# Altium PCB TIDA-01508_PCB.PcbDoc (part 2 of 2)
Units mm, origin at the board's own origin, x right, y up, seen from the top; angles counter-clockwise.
Board outline 58.5 x 103 mm, 4 copper layers (Top Layer, GND, VCC, Bottom Layer), stack 1.565 mm thick; 194 components, 119 nets, 642 pads, 130 vias.
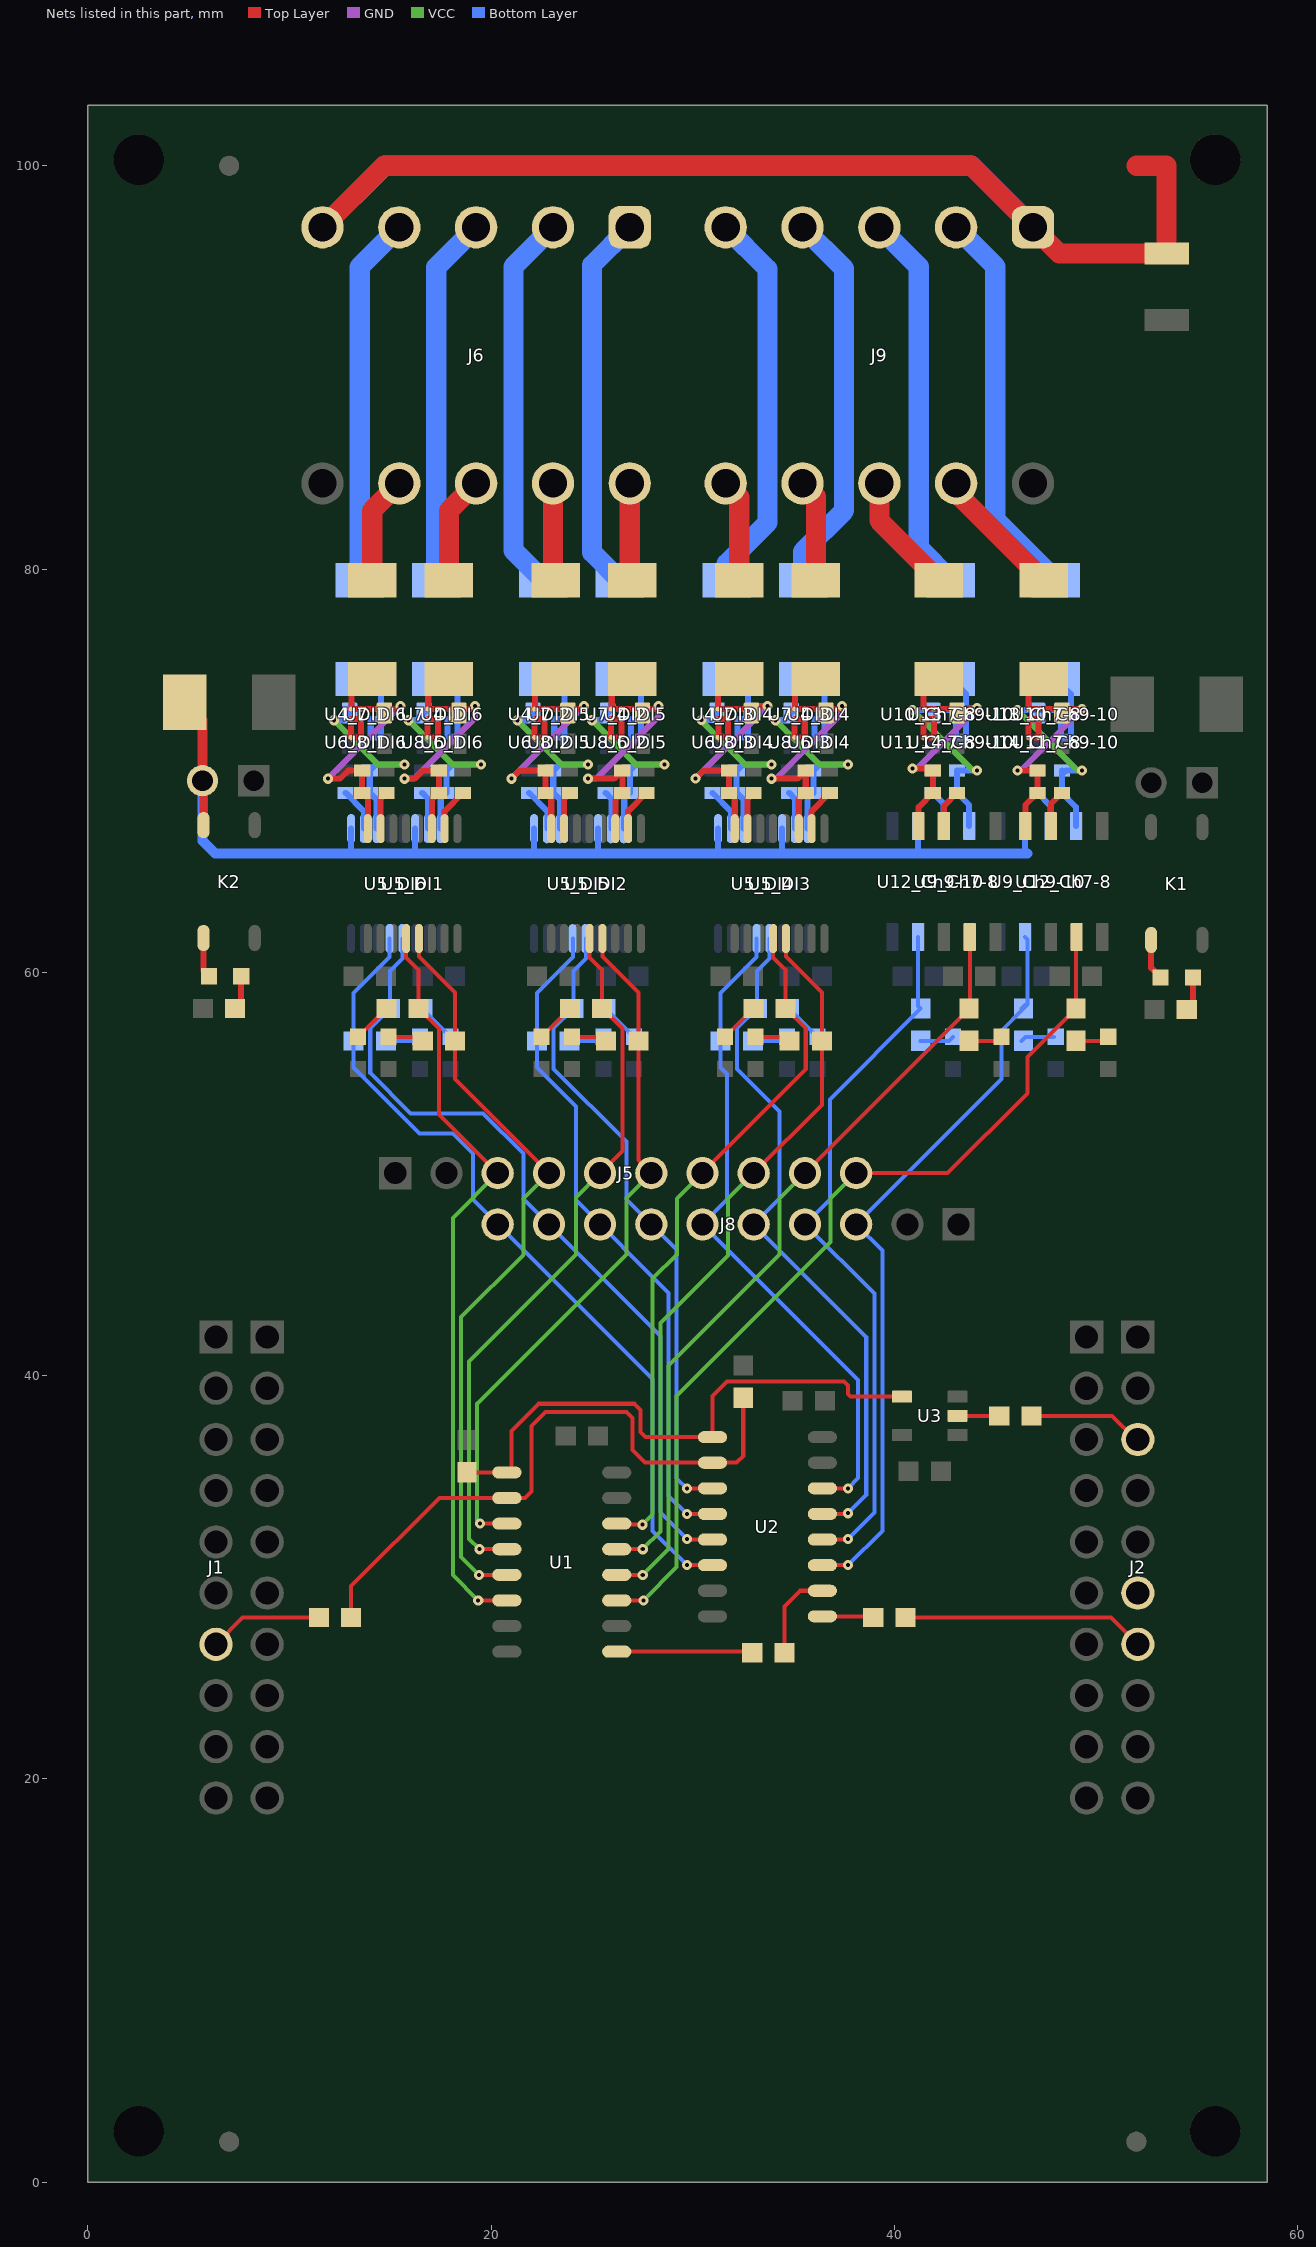
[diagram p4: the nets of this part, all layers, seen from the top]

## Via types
v1: diameter 0.5, hole 0.2, Top Layer to Bottom Layer, 129 vias
v2: diameter 0.7, hole 0.4, Top Layer to Bottom Layer, 1 vias

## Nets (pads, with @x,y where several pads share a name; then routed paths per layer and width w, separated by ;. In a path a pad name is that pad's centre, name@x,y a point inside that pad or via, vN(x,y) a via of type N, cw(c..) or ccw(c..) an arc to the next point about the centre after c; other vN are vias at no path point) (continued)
FGND_float9-16: D4.2 J10.2 K2.4 U5_DI4.9 U5_DI4.14 U5_DI5.9 U5_DI5.14 U5_DI6.9 U5_DI6.14 U9_Ch9-10.6 U12_Ch9-10.6 | length 60.1
  Top Layer w0.4: J10.2@5.68,69.5 5.73,69.45 K2.4@5.73,67.3
  Top Layer w0.5: D4.2@4.79,73.4 5.68,72.51 J10.2@5.68,69.5
  Bottom Layer w0.3: 13.052,65.948 U5_DI6.9@13.052,67.125 ; 16.227,65.927 U5_DI6.14@16.227,67.125 ; 22.126,66.026 U5_DI5.9@22.126,67.119 ; 25.301,65.901 U5_DI5.14@25.301,67.119 ; 31.252,65.952 U5_DI4.9@31.252,67.125 ; 34.427,66.027 U5_DI4.14@34.427,67.125 ; 41.165,65.965 U12_Ch9-10.6@41.165,67.25 ; 46.465,66.065 U9_Ch9-10.6@46.465,67.25
  Bottom Layer w0.5: J10.2@5.68,69.5 5.68,66.52 6.3,65.9 46.6,65.9
IN11: J6.8 R9_DI1.2 | length 5.4
  Top Layer w1: R9_DI1.2@14.1,79.45 14.1,82.91 J6.8@15.44,84.25
IN12: J6.4 R9_DI2.2 | length 4.9
  Top Layer w1: J6.4@23.06,84.25 23.06,79.59 R9_DI2.2@23.2,79.45
IN13: J9.10 R9_DI3.2 | length 5.1
  Top Layer w1: J9.10@31.63,84.25 32.3,83.58 R9_DI3.2@32.3,79.45
IN14: J9.7 R9_DI4.2 | length 19.2
  Bottom Layer w1: J9.7@35.44,96.95 37.5,94.89 37.5,82.9 35.475,80.875 R9_DI4.2@35.475,79.45
IN15: J6.1 R9_DI5.2 | length 18.8
  Bottom Layer w1: R9_DI5.2@26.375,79.45 25,80.825 25,95.08 J6.1@26.87,96.95
IN16: J6.5 R9_DI6.2 | length 18.3
  Bottom Layer w1: R9_DI6.2@17.275,79.45 17.275,94.975 J6.5@19.25,96.95
IN21: J6.6 R11_DI1.2 | length 5.4
  Top Layer w1: R11_DI1.2@17.9,79.45 17.9,82.9 J6.6@19.25,84.25
IN22: J6.2 R11_DI2.2 | length 4.9
  Top Layer w1: J6.2@26.87,84.25 26.87,79.58 R11_DI2.2@27,79.45
IN23: J9.8 R11_DI3.2 | length 5.1
  Top Layer w1: J9.8@35.44,84.25 36.1,83.59 R11_DI3.2@36.1,79.45
IN24: J9.9 R11_DI4.2 | length 19.2
  Bottom Layer w1: J9.9@31.63,96.95 33.7,94.88 33.7,82.3 31.675,80.275 R11_DI4.2@31.675,79.45
IN25: J6.3 R11_DI5.2 | length 18.9
  Bottom Layer w1: R11_DI5.2@22.575,79.45 21.1,80.925 21.1,94.99 J6.3@23.06,96.95
IN26: J6.7 R11_DI6.2 | length 18.3
  Bottom Layer w1: R11_DI6.2@13.475,79.45 13.475,94.985 J6.7@15.44,96.95
INCh7: J9.6 R15_Ch7-8.2 | length 6
  Top Layer w1: J9.6@39.25,84.25 39.25,82.4 R15_Ch7-8.2@42.2,79.45
INCh8: J9.4 R18_Ch7-8.2 | length 6.6
  Top Layer w1: J9.4@43.06,84.25 43.06,83.79 R18_Ch7-8.2@47.4,79.45
InCh9: J9.3 R15_Ch9-10.2 | length 19.5
  Bottom Layer w1: J9.3@43.06,96.95 45,95.01 45,82.45 R15_Ch9-10.2@48,79.45
InCh10: J9.5 R18_Ch9-10.2 | length 19
  Bottom Layer w1: J9.5@39.25,96.95 41.2,95 41.2,81.05 R18_Ch9-10.2@42.8,79.45
NetC6_DI1_2: C6_DI1.2 D5_DI1.2 R9_DI1.1 R10_DI1.2 U4_DI1.A1 U4_DI1.A2 U5_DI1.16 | length 14.7
  Top Layer w0.3: v1(11.9,69.6) 12.5,69.6 12.9,70 C6_DI1.2@13.6,70 R10_DI1.2@13.6,68.9 13.878,68.622 U5_DI1.16@13.878,67.125 ; U4_DI1.A1@13.05,73.05 U4_DI1.A2@13.55,73.05 v1@15.35,73.05 ; U4_DI1.A1@13.077,73.077 13.077,74.55 R9_DI1.1@14.1,74.55
  GND w0.3: v1(11.9,69.6) v1(15.5,73.2)
NetC6_DI2_2: C6_DI2.2 D5_DI2.2 R9_DI2.1 R10_DI2.2 U4_DI2.A1 U4_DI2.A2 U5_DI2.16 | length 15
  Top Layer w0.3: v1(21,69.6) 21.4,70 C6_DI2.2@22.7,70 R10_DI2.2@22.7,68.9 22.978,68.622 U5_DI2.16@22.978,67.125 ; U4_DI2.A1@22.15,73.05 U4_DI2.A2@22.65,73.05 24.45,73.05 v1(24.6,73.2) ; U4_DI2.A1@22.177,73.077 22.177,74.55 R9_DI2.1@23.2,74.55
  GND w0.3: v1(21,69.6) v1(24.6,73.2)
NetC6_DI3_2: C6_DI3.2 D5_DI3.2 R9_DI3.1 R10_DI3.2 U4_DI3.A1 U4_DI3.A2 U5_DI3.16 | length 14.4
  Top Layer w0.3: v1(30.127,69.606) 30.521,70 C6_DI3.2@31.8,70 R10_DI3.2@31.8,68.9 32.078,68.622 U5_DI3.16@32.078,67.125 ; R9_DI3.1@32.169,74.419 31.568,74.419 31.25,74.101 U4_DI3.A1@31.25,73.05 U4_DI3.A2@31.75,73.05 D5_DI3.2@32.71,73.05 ; D5_DI3.2@32.9,72.86 33.24,73.2 v1(33.7,73.2)
  GND w0.3: v1(30.127,69.606) v1@33.7,73.179
NetC6_DI4_2: C6_DI4.2 D5_DI4.2 R9_DI4.1 R10_DI4.2 U4_DI4.A1 U4_DI4.A2 U5_DI4.16 | length 14.3
  VCC w0.3: v1(34.1,72.5) 36.3,70.3 v1(37.7,70.3)
  Bottom Layer w0.3: v1(34.1,72.5) 34.515,72.5 D5_DI4.2@34.875,72.86 35.065,73.05 U4_DI4.A2@36.025,73.05 U4_DI4.A1@36.525,73.05 36.525,74.175 36.5,74.2 35.825,74.2 R9_DI4.1@35.475,74.55 ; U5_DI4.16@35.697,67.125 35.697,68.622 R10_DI4.2@35.975,68.9 C6_DI4.2@35.975,70 36.275,70.3 v1(37.7,70.3)
NetC6_DI5_2: C6_DI5.2 D5_DI5.2 R9_DI5.1 R10_DI5.2 U4_DI5.A1 U4_DI5.A2 U5_DI5.16 | length 14.3
  VCC w0.3: v1(25,72.5) 27.2,70.3 v1(28.6,70.3)
  Bottom Layer w0.3: v1(25,72.5) 25.415,72.5 D5_DI5.2@25.775,72.86 25.965,73.05 U4_DI5.A2@26.925,73.05 U4_DI5.A1@27.425,73.05 27.425,74.175 27.4,74.2 26.725,74.2 R9_DI5.1@26.375,74.55 ; U5_DI5.16@26.597,67.125 26.597,68.622 R10_DI5.2@26.875,68.9 C6_DI5.2@26.875,70 27.175,70.3 v1(28.6,70.3)
NetC6_DI6_2: C6_DI6.2 D5_DI6.2 R9_DI6.1 R10_DI6.2 U4_DI6.A1 U4_DI6.A2 U5_DI6.16 | length 14.3
  VCC w0.3: v1(15.9,72.5) 18.1,70.3 v1(19.5,70.3)
  Bottom Layer w0.3: v1(15.9,72.5) 16.315,72.5 D5_DI6.2@16.675,72.86 16.865,73.05 U4_DI6.A2@17.825,73.05 U4_DI6.A1@18.325,73.05 18.325,74.175 18.3,74.2 17.625,74.2 R9_DI6.1@17.275,74.55 ; U5_DI6.16@17.497,67.125 17.497,68.622 R10_DI6.2@17.775,68.9 C6_DI6.2@17.775,70 18.075,70.3 v1(19.5,70.3)
NetC7_DI1_2: C7_DI1.2 D6_DI1.2 R11_DI1.1 R12_DI1.2 U5_DI1.11 U7_DI1.A1 U7_DI1.A2 | length 15.1
  Top Layer w0.3: v1(15.7,69.6) 16.2,69.6 16.6,70 C7_DI1.2@17.4,70 R12_DI1.2@17.4,68.9 17.053,68.553 U5_DI1.11@17.053,67.125 ; U7_DI1.A1@16.85,73.05 U7_DI1.A2@17.35,73.05 19.05,73.05 v1(19.2,73.2) ; U7_DI1.A1@16.877,73.077 16.877,74.55 R11_DI1.1@17.9,74.55
  GND w0.3: v1(15.7,69.6) 16.175,69.6 19.2,72.625 v1(19.2,73.2)
NetC7_DI2_2: C7_DI2.2 D6_DI2.2 R11_DI2.1 R12_DI2.2 U5_DI2.11 U7_DI2.A1 U7_DI2.A2 | length 15.1
  Top Layer w0.3: v1(24.8,69.6) 26.1,69.6 C7_DI2.2@26.5,70 R12_DI2.2@26.5,68.9 26.153,68.553 U5_DI2.11@26.153,67.125 ; U7_DI2.A1@25.95,73.05 U7_DI2.A2@26.45,73.05 28.15,73.05 v1(28.3,73.2) ; U7_DI2.A1@25.977,73.077 25.977,74.55 R11_DI2.1@27,74.55
  GND w0.3: v1(24.8,69.6) 25.2,69.6 28.3,72.7 v1(28.3,73.2)
NetC7_DI3_2: C7_DI3.2 D6_DI3.2 R11_DI3.1 R12_DI3.2 U5_DI3.11 U7_DI3.A1 U7_DI3.A2 | length 15
  Top Layer w0.3: v1(33.9,69.6) 35.2,69.6 C7_DI3.2@35.6,70 R12_DI3.2@35.6,68.9 35.253,68.553 U5_DI3.11@35.253,67.125 ; U7_DI3.A1@35.05,73.05 37.25,73.05 v1(37.4,73.2) ; U7_DI3.A1@35.077,73.077 35.077,74.55 R11_DI3.1@36.1,74.55
  GND w0.3: v1(33.9,69.6) 34.125,69.6 37.4,72.875 v1(37.4,73.2)
NetC7_DI4_2: C7_DI4.2 D6_DI4.2 R11_DI4.1 R12_DI4.2 U5_DI4.11 U7_DI4.A1 U7_DI4.A2 | length 14.3
  VCC w0.3: v1@30.4,72.5 32.6,70.3 v1(33.9,70.3)
  Bottom Layer w0.3: v1(30.427,72.506) 30.842,72.506 D6_DI4.2@31.202,72.866 D6_DI4.2@31.392,73.056 ; D6_DI4.2@31.365,73.05 U7_DI4.A2@32.225,73.05 U7_DI4.A1@32.725,73.05 32.725,74.375 32.55,74.55 R11_DI4.1@31.675,74.55 ; U5_DI4.11@32.522,67.125 32.522,68.553 R12_DI4.2@32.175,68.9 C7_DI4.2@32.175,70 32.475,70.3 v1(33.9,70.3)
NetC7_DI5_2: C7_DI5.2 D6_DI5.2 R11_DI5.1 R12_DI5.2 U5_DI5.11 U7_DI5.A1 U7_DI5.A2 | length 14.3
  VCC w0.3: v1(21.3,72.5) 23.5,70.3 v1(24.8,70.3)
  Bottom Layer w0.3: v1(21.3,72.5) 21.715,72.5 D6_DI5.2@22.075,72.86 22.265,73.05 U7_DI5.A2@23.125,73.05 U7_DI5.A1@23.625,73.05 23.625,74.375 23.45,74.55 R11_DI5.1@22.575,74.55 ; U5_DI5.11@23.422,67.125 23.422,68.553 R12_DI5.2@23.075,68.9 C7_DI5.2@23.075,70 23.375,70.3 v1(24.8,70.3)
NetC7_DI6_2: C7_DI6.2 D6_DI6.2 R11_DI6.1 R12_DI6.2 U5_DI6.11 U7_DI6.A1 U7_DI6.A2 | length 14.3
  VCC w0.3: v1(12.2,72.5) 14.4,70.3 v1(15.7,70.3)
  Bottom Layer w0.3: v1(12.2,72.5) 12.615,72.5 D6_DI6.2@12.975,72.86 13.165,73.05 U7_DI6.A2@14.025,73.05 U7_DI6.A1@14.525,73.05 14.525,74.375 14.35,74.55 R11_DI6.1@13.475,74.55 ; U5_DI6.11@14.322,67.125 14.322,68.553 R12_DI6.2@13.975,68.9 C7_DI6.2@13.975,70 14.275,70.3 v1(15.7,70.3)
NetC10_Ch7-8_2: C10_Ch7-8.2 D9_Ch7-8.2 R15_Ch7-8.1 R16_Ch7-8.2 U9_Ch7-8.8 U10_Ch7-8.A1 U10_Ch7-8.A2 | length 13
  Top Layer w0.3: v1(40.9,70.1) 41.8,70.1 C10_Ch7-8.2@41.9,70 R16_Ch7-8.2@41.9,68.9 41.195,68.195 U9_Ch7-8.8@41.195,67.25 ; R15_Ch7-8.1@42.2,74.55 41.45,73.8 U10_Ch7-8.A1@41.45,73.05 U10_Ch7-8.A2@41.95,73.05 42.91,73.05 42.96,73.1 v1(44.1,73.1)
  GND w0.3: v1(40.9,70.1) 41.1,70.1 v1(44.1,73.1)
NetC10_Ch9-10_2: C10_Ch9-10.2 D9_Ch9-10.2 R15_Ch9-10.1 R16_Ch9-10.2 U9_Ch9-10.8 U10_Ch9-10.A1 U10_Ch9-10.A2 | length 13.1
  VCC w0.3: v1(46.1,73) 49.1,70 v1(49.3,70)
  Bottom Layer w0.3: v1(46.1,73) 48.1,73 48.2,73.1 U10_Ch9-10.A2@48.25,73.05 U10_Ch9-10.A1@48.75,73.05 48.75,73.8 R15_Ch9-10.1@48,74.55 ; U9_Ch9-10.8@49.005,67.25 49.005,68.195 R16_Ch9-10.2@48.3,68.9 C10_Ch9-10.2@48.3,70 48.4,69.9 48.5,70 v1(49.3,70)
NetC11_Ch7-8_2: C11_Ch7-8.2 D11_Ch7-8.2 R18_Ch7-8.1 R19_Ch7-8.2 U12_Ch7-8.8 U13_Ch7-8.A1 U13_Ch7-8.A2 | length 12.9
  Top Layer w0.3: v1(46.1,70) C11_Ch7-8.2@47.1,70 R19_Ch7-8.2@47.1,68.9 46.495,68.295 U12_Ch7-8.8@46.495,67.25 ; R18_Ch7-8.1@47.4,74.55 46.65,73.8 U13_Ch7-8.A1@46.65,73.05 U13_Ch7-8.A2@47.15,73.05 48.11,73.05 v1(49.3,73.05)
  GND w0.3: v1(46.1,70) 46.25,70 v1(49.3,73.05)
NetC11_Ch9-10_2: C11_Ch9-10.2 D11_Ch9-10.2 R18_Ch9-10.1 R19_Ch9-10.2 U12_Ch9-10.8 U13_Ch9-10.A1 U13_Ch9-10.A2 | length 13
  VCC w0.3: v1(40.9,73) 43.9,70 v1(44.1,70)
  Bottom Layer w0.3: v1(40.9,73) 42.8,73 42.9,73.1 43,73 U13_Ch9-10.A2@43.05,73.05 U13_Ch9-10.A1@43.55,73.05 43.55,73.8 R18_Ch9-10.1@42.8,74.55 ; U12_Ch9-10.8@43.705,67.25 43.705,68.295 R19_Ch9-10.2@43.1,68.9 C11_Ch9-10.2@43.1,70 v1(44.1,70)
NetD1_1: D1.1 K1.1 | length 2
  Top Layer w0.3: K1.1@52.73,61.6 52.73,60.22 D1.1@53.2,59.75
NetD1_2: D1.2 R1.2 | length 1.7
  Top Layer w0.3: R1.2@54.5,58.15 54.8,58.45 D1.2@54.8,59.75
NetD3_1: D3.1 K2.1 | length 2
  Top Layer w0.3: K2.1@5.73,61.7 5.73,60.07 D3.1@6,59.8
NetD3_2: D3.2 R5.2 | length 1.7
  Top Layer w0.3: R5.2@7.3,58.2 7.6,58.5 D3.2@7.6,59.8
NetD7_DI1_2: D7_DI1.2 R13_DI1.1 | length 2
  Top Layer w0.2: D7_DI1.2@13.4,56.8 R13_DI1.1@14.8,58.2
NetD7_DI2_2: D7_DI2.2 R13_DI2.1 | length 2
  Top Layer w0.2: D7_DI2.2@22.5,56.8 R13_DI2.1@23.9,58.2
NetD7_DI3_2: D7_DI3.2 R13_DI3.1 | length 2
  Top Layer w0.2: D7_DI3.2@31.6,56.8 R13_DI3.1@33,58.2
NetD7_DI4_2: D7_DI4.2 R13_DI4.1 | length 2
  Bottom Layer w0.2: R13_DI4.1@34.775,58.2 D7_DI4.2@36.175,56.8
NetD7_DI5_2: D7_DI5.2 R13_DI5.1 | length 2
  Bottom Layer w0.2: R13_DI5.1@25.675,58.2 D7_DI5.2@27.075,56.8
NetD7_DI6_2: D7_DI6.2 R13_DI6.1 | length 2
  Bottom Layer w0.2: R13_DI6.1@16.575,58.2 D7_DI6.2@17.975,56.8
NetD8_DI1_2: D8_DI1.2 R14_DI1.1 | length 1.8
  Top Layer w0.2: D8_DI1.2@14.9,56.8 16.4,56.8 R14_DI1.1@16.6,56.6
NetD8_DI2_2: D8_DI2.2 R14_DI2.1 | length 1.8
  Top Layer w0.2: D8_DI2.2@24,56.8 25.5,56.8 R14_DI2.1@25.7,56.6
NetD8_DI3_2: D8_DI3.2 R14_DI3.1 | length 1.8
  Top Layer w0.2: D8_DI3.2@33.1,56.8 34.6,56.8 R14_DI3.1@34.8,56.6
NetD8_DI4_2: D8_DI4.2 R14_DI4.1 | length 1.8
  Bottom Layer w0.2: R14_DI4.1@32.975,56.6 34.475,56.6 D8_DI4.2@34.675,56.8
NetD8_DI5_2: D8_DI5.2 R14_DI5.1 | length 1.8
  Bottom Layer w0.2: R14_DI5.1@23.875,56.6 25.375,56.6 D8_DI5.2@25.575,56.8
NetD8_DI6_2: D8_DI6.2 R14_DI6.1 | length 1.8
  Bottom Layer w0.2: R14_DI6.1@14.775,56.6 16.275,56.6 D8_DI6.2@16.475,56.8
NetD10_Ch7-8_2: D10_Ch7-8.2 R17_Ch7-8.1 | length 1.7
  Top Layer w0.2: R17_Ch7-8.1@43.7,56.6 45.1,56.6 D10_Ch7-8.2@45.3,56.8
NetD10_Ch9-10_2: D10_Ch9-10.2 R17_Ch9-10.1 | length 1.7
  Bottom Layer w0.2: R17_Ch9-10.1@46.3,56.6 46.5,56.8 D10_Ch9-10.2@47.9,56.8
NetD12_Ch7-8_2: D12_Ch7-8.2 R20_Ch7-8.1 | length 1.7
  Top Layer w0.2: R20_Ch7-8.1@49,56.6 50.4,56.6 D12_Ch7-8.2@50.6,56.8
NetD12_Ch9-10_2: D12_Ch9-10.2 R20_Ch9-10.1 | length 1.7
  Bottom Layer w0.2: R20_Ch9-10.1@41.3,56.6 42.7,56.6 D12_Ch9-10.2@42.9,56.8
NetR2_1: R2.1 U2.10 | length 4.5
  Top Layer w0.2: R2.1@34.55,26.25 34.55,28.55 35.325,29.325 U2.10@36.425,29.325
NetR2_2: R2.2 U1.9 | length 6.7
  Top Layer w0.2: U1.9@26.225,26.305 R2.2@32.895,26.305
NetR3_2: R3.2 U2.9 | length 2.5
  Top Layer w0.2: U2.9@36.425,28.055 R3.2@38.895,28.055
NetR4_2: R4.2 U3.2 | length 2.1
  Top Layer w0.2: U3.2@43.125,38 R4.2@45.2,38
NetR6_2: R6.2 R7.2 U1.2 U2.2 | length 31.5
  Top Layer w0.2: R6.2@13.05,28 13.05,29.55 17.425,33.925 21.675,33.925 22,34.25 22,37.5 22.7,38.2 26.7,38.2 27,37.9 27,36.3 27.625,35.675 U2.2@30.975,35.675 32.175,35.675 32.5,36 R7.2@32.5,38.9
NetR8_2: R8.2 U1.1 U2.1 U3.4 | length 28.4
  Top Layer w0.2: R8.2@18.805,35.195 21,35.195 21,37.25 22.35,38.6 27.1,38.6 27.4,38.3 27.4,37.2 27.655,36.945 U2.1@30.975,36.945 30.975,38.975 31.7,39.7 37.5,39.7 37.7,39.5 37.7,39.075 37.825,38.95 U3.4@40.375,38.95
NetR10_DI1_1: R10_DI1.1 U5_DI1.15 | length 1.9
  Top Layer w0.3: U5_DI1.15@14.513,67.125 14.513,68.613 R10_DI1.1@14.8,68.9
NetR10_DI2_1: R10_DI2.1 U5_DI2.15 | length 1.9
  Top Layer w0.3: U5_DI2.15@23.613,67.125 23.613,68.613 R10_DI2.1@23.9,68.9
NetR10_DI3_1: R10_DI3.1 U5_DI3.15 | length 1.9
  Top Layer w0.3: U5_DI3.15@32.713,67.125 32.712,68.613 R10_DI3.1@33,68.9
NetR10_DI4_1: R10_DI4.1 U5_DI4.15 | length 1.9
  Bottom Layer w0.3: R10_DI4.1@34.775,68.9 35.062,68.613 U5_DI4.15@35.062,67.125
NetR10_DI5_1: R10_DI5.1 U5_DI5.15 | length 1.9
  Bottom Layer w0.3: R10_DI5.1@25.675,68.9 25.962,68.613 U5_DI5.15@25.962,67.125
NetR10_DI6_1: R10_DI6.1 U5_DI6.15 | length 1.9
  Bottom Layer w0.3: R10_DI6.1@16.575,68.9 16.862,68.613 U5_DI6.15@16.862,67.125
NetR12_DI1_1: R12_DI1.1 U5_DI1.10 | length 2.2
  Top Layer w0.3: U5_DI1.10@17.688,67.125 17.688,67.988 R12_DI1.1@18.6,68.9
NetR12_DI2_1: R12_DI2.1 U5_DI2.10 | length 3
  Top Layer w0.3: R12_DI2.1@27.7,68.9 26.788,67.988 ; 26.788,67.988 U5_DI2.10@26.788,67.125 26.788,67.988
NetR12_DI3_1: R12_DI3.1 U5_DI3.10 | length 2.2
  Top Layer w0.3: U5_DI3.10@35.888,67.125 35.887,67.988 R12_DI3.1@36.8,68.9
NetR12_DI4_1: R12_DI4.1 U5_DI4.10 | length 2.2
  Bottom Layer w0.3: R12_DI4.1@30.975,68.9 31.887,67.988 U5_DI4.10@31.887,67.125
NetR12_DI5_1: R12_DI5.1 U5_DI5.10 | length 2.2
  Bottom Layer w0.3: R12_DI5.1@21.875,68.9 22.787,67.988 U5_DI5.10@22.787,67.125
NetR12_DI6_1: R12_DI6.1 U5_DI6.10 | length 2.2
  Bottom Layer w0.3: R12_DI6.1@12.775,68.9 13.687,67.988 U5_DI6.10@13.687,67.125
NetR16_Ch7-8_1: R16_Ch7-8.1 U9_Ch7-8.7 | length 1.9
  Top Layer w0.3: U9_Ch7-8.7@42.465,67.25 42.465,68.265 R16_Ch7-8.1@43.1,68.9
NetR16_Ch9-10_1: R16_Ch9-10.1 U9_Ch9-10.7 | length 1.9
  Bottom Layer w0.3: R16_Ch9-10.1@47.1,68.9 47.735,68.265 U9_Ch9-10.7@47.735,67.25
NetR19_Ch7-8_1: R19_Ch7-8.1 U12_Ch7-8.7 | length 1.9
  Top Layer w0.3: U12_Ch7-8.7@47.765,67.25 47.765,68.365 R19_Ch7-8.1@48.3,68.9
NetR19_Ch9-10_1: R19_Ch9-10.1 U12_Ch9-10.7 | length 1.9
  Bottom Layer w0.3: R19_Ch9-10.1@41.9,68.9 42.435,68.365 U12_Ch9-10.7@42.435,67.25
NetU4_DI1_B1: U4_DI1.B1 U4_DI1.B2 U6_DI1.B1 U6_DI1.B2 | length 2.8
  Top Layer w0.3: U6_DI1.B2@13.05,71.65 U6_DI1.B1@13.55,71.65 U4_DI1.B2@13.55,72.55 U4_DI1.B1@13.05,72.55 U6_DI1.B2@13.05,71.65
NetU4_DI2_B1: U4_DI2.B1 U4_DI2.B2 U6_DI2.B1 U6_DI2.B2 | length 2.8
  Top Layer w0.3: U6_DI2.B2@22.15,71.65 U4_DI2.B1@22.15,72.55 U4_DI2.B2@22.65,72.55 U6_DI2.B1@22.65,71.65 U6_DI2.B2@22.15,71.65
NetU4_DI3_B1: U4_DI3.B1 U4_DI3.B2 U6_DI3.B1 U6_DI3.B2 | length 2.8
  Top Layer w0.3: U6_DI3.B2@31.25,71.65 U6_DI3.B1@31.75,71.65 U4_DI3.B2@31.75,72.55 U4_DI3.B1@31.25,72.55 ; U6_DI3.B2@31.277,71.656 U4_DI3.B1@31.277,72.556
NetU4_DI4_B1: U4_DI4.B1 U4_DI4.B2 U6_DI4.B1 U6_DI4.B2 | length 2.8
  Bottom Layer w0.3: U6_DI4.B1@36.025,71.65 U4_DI4.B2@36.025,72.55 U4_DI4.B1@36.525,72.55 U6_DI4.B2@36.525,71.65 U6_DI4.B1@36.025,71.65
NetU4_DI5_B1: U4_DI5.B1 U4_DI5.B2 U6_DI5.B1 U6_DI5.B2 | length 2.8
  Bottom Layer w0.3: U6_DI5.B1@26.925,71.65 U4_DI5.B2@26.925,72.55 U4_DI5.B1@27.425,72.55 U6_DI5.B2@27.425,71.65 U6_DI5.B1@26.925,71.65
NetU4_DI6_B1: U4_DI6.B1 U4_DI6.B2 U6_DI6.B1 U6_DI6.B2 | length 2.8
  Bottom Layer w0.3: U6_DI6.B1@17.825,71.65 U6_DI6.B2@18.325,71.65 U4_DI6.B1@18.325,72.55 U4_DI6.B2@17.825,72.55 U6_DI6.B1@17.825,71.65
NetU7_DI1_B1: U7_DI1.B1 U7_DI1.B2 U8_DI1.B1 U8_DI1.B2 | length 2.8
  Top Layer w0.3: U8_DI1.B2@16.85,71.65 U7_DI1.B1@16.85,72.55 U7_DI1.B2@17.35,72.55 U8_DI1.B1@17.35,71.65 U8_DI1.B2@16.85,71.65
NetU7_DI2_B1: U7_DI2.B1 U7_DI2.B2 U8_DI2.B1 U8_DI2.B2 | length 2.8
  Top Layer w0.3: U8_DI2.B2@25.95,71.65 U8_DI2.B1@26.45,71.65 U7_DI2.B2@26.45,72.55 U7_DI2.B1@25.95,72.55 U8_DI2.B2@25.95,71.65
NetU7_DI3_B1: U7_DI3.B1 U7_DI3.B2 U8_DI3.B1 U8_DI3.B2 | length 2.8
  Top Layer w0.3: U8_DI3.B2@35.05,71.65 U8_DI3.B1@35.55,71.65 U7_DI3.B2@35.55,72.55 U7_DI3.B1@35.05,72.55 U8_DI3.B2@35.05,71.65
NetU7_DI4_B1: U7_DI4.B1 U7_DI4.B2 U8_DI4.B1 U8_DI4.B2 | length 2.8
  Bottom Layer w0.3: U8_DI4.B1@32.225,71.65 U7_DI4.B2@32.225,72.55 U7_DI4.B1@32.725,72.55 U8_DI4.B2@32.725,71.65 U8_DI4.B1@32.225,71.65
NetU7_DI5_B1: U7_DI5.B1 U7_DI5.B2 U8_DI5.B1 U8_DI5.B2 | length 2.8
  Bottom Layer w0.3: U8_DI5.B1@23.125,71.65 U7_DI5.B2@23.125,72.55 U7_DI5.B1@23.625,72.55 U8_DI5.B2@23.625,71.65 U8_DI5.B1@23.125,71.65
NetU7_DI6_B1: U7_DI6.B1 U7_DI6.B2 U8_DI6.B1 U8_DI6.B2 | length 2.8
  Bottom Layer w0.3: U8_DI6.B1@14.025,71.65 U8_DI6.B2@14.525,71.65 U7_DI6.B1@14.525,72.55 U7_DI6.B2@14.025,72.55 U8_DI6.B1@14.025,71.65
NetU10_Ch7-8_B1: U10_Ch7-8.B1 U10_Ch7-8.B2 U11_Ch7-8.B1 U11_Ch7-8.B2 | length 2.8
  Top Layer w0.3: U11_Ch7-8.B2@41.45,71.65 U11_Ch7-8.B1@41.95,71.65 U10_Ch7-8.B2@41.95,72.55 U10_Ch7-8.B1@41.45,72.55 U11_Ch7-8.B2@41.45,71.65
NetU10_Ch9-10_B1: U10_Ch9-10.B1 U10_Ch9-10.B2 U11_Ch9-10.B1 U11_Ch9-10.B2 | length 2.8
  Bottom Layer w0.3: U11_Ch9-10.B1@48.25,71.65 U10_Ch9-10.B2@48.25,72.55 U10_Ch9-10.B1@48.75,72.55 U11_Ch9-10.B2@48.75,71.65 U11_Ch9-10.B1@48.25,71.65
NetU13_Ch7-8_B1: U13_Ch7-8.B1 U13_Ch7-8.B2 U14_Ch7-8.B1 U14_Ch7-8.B2 | length 2.8
  Top Layer w0.3: U14_Ch7-8.B2@46.65,71.65 U14_Ch7-8.B1@47.15,71.65 U13_Ch7-8.B2@47.15,72.55 U13_Ch7-8.B1@46.65,72.55 U14_Ch7-8.B2@46.65,71.65
NetU13_Ch9-10_B1: U13_Ch9-10.B1 U13_Ch9-10.B2 U14_Ch9-10.B1 U14_Ch9-10.B2 | length 2.8
  Bottom Layer w0.3: U14_Ch9-10.B1@43.05,71.65 U13_Ch9-10.B2@43.05,72.55 U13_Ch9-10.B1@43.55,72.55 U14_Ch9-10.B2@43.55,71.65 U14_Ch9-10.B1@43.05,71.65
OUT11: J5.3 R13_DI1.2 U1.6 U5_DI1.4 | length 37.6
  Top Layer w0.2: U5_DI1.4@15.783,61.675 15.783,60.742 16.4,60.125 R13_DI1.2@16.4,58.2 17.4,57.2 17.4,52.958 J5.3@20.32,50.038 ; v1(19.355,28.845) U1.6@20.775,28.845
  VCC w0.2: v1(19.355,28.845) 18.1,30.1 18.1,47.818 J5.3@20.32,50.038
OUT12: J5.5 R13_DI2.2 U1.4 U5_DI2.4 | length 35.7
  Top Layer w0.2: v1(19.415,31.385) U1.4@20.775,31.385 ; U5_DI2.4@24.883,61.675 24.883,60.742 25.5,60.125 R13_DI2.2@25.5,58.2 26.5,57.2 26.5,51.138 J5.5@25.4,50.038
  VCC w0.2: v1(19.415,31.385) 18.9,31.9 18.9,40.7 24.2,46 24.2,48.838 J5.5@25.4,50.038
OUT13: J5.7 R13_DI3.2 U1.14 U5_DI3.4 | length 34.4
  Top Layer w0.2: U1.14@26.225,32.655 26.28,32.6 v1(27.5,32.6) ; J5.7@30.48,50.038 30.48,50.08 35.6,55.2 35.6,57.2 R13_DI3.2@34.6,58.2 34.6,60.125 33.982,60.742 U5_DI3.4@33.983,61.675
  VCC w0.2: v1(27.5,32.6) 28,33.1 28,44.8 29.21,46.01 29.21,48.768 J5.7@30.48,50.038
OUT14: J8.5 R13_DI4.2 U2.13 U5_DI4.4 | length 35.2
  Top Layer w0.2: U2.13@36.425,33.135 37.665,33.135 v1(37.7,33.17)
  Bottom Layer w0.2: U5_DI4.4@33.792,61.675 33.792,60.692 33.175,60.075 R13_DI4.2@33.175,58.2 32.2,57.225 32.2,55.2 34.3,53.1 34.3,48.78 33.02,47.5 38.6,41.92 38.6,34.07 v1(37.7,33.17) 38.2,33.67
OUT15: J8.7 R13_DI5.2 U2.3 U5_DI5.4 | length 32.1
  Top Layer w0.2: v1(29.7,34.4) 30.97,34.4 U2.3@30.975,34.405
  Bottom Layer w0.2: U5_DI5.4@24.692,61.675 24.692,60.692 24.075,60.075 R13_DI5.2@24.075,58.2 23.1,57.225 23.1,55.2 26.7,51.6 26.7,48.74 29.2,46.24 29.2,34.9 v1(29.7,34.4) v1@29.6,34.5
OUT16: J8.9 R13_DI6.2 U2.5 U5_DI6.4 | length 40.3
  Top Layer w0.2: v1(29.7,31.9) 29.735,31.865 U2.5@30.975,31.865
  Bottom Layer w0.2: U5_DI6.4@15.592,61.675 15.592,60.692 14.975,60.075 R13_DI6.2@14.975,58.2 14,57.225 14,55 16,53 19.6,53 21.6,51 21.6,48.76 28.4,41.96 28.4,33.2 v1(29.7,31.9)
OUT21: J5.4 R14_DI1.2 U1.5 U5_DI1.5 | length 37.8
  Top Layer w0.2: U5_DI1.5@16.418,61.675 16.418,60.782 18.2,59 R14_DI1.2@18.2,56.6 18.2,54.698 J5.4@22.86,50.038 ; v1(19.385,30.115) U1.5@20.775,30.115
  VCC w0.2: v1(19.385,30.115) 18.5,31 18.5,42.9 21.59,45.99 21.59,48.768 J5.4@22.86,50.038
OUT22: J5.6 R14_DI2.2 U1.3 U5_DI2.5 | length 35
  Top Layer w0.2: v1(19.445,32.655) U1.3@20.775,32.655 ; U5_DI2.5@25.518,61.675 25.518,60.782 27.3,59 R14_DI2.2@27.3,56.6 27.3,50.678 J5.6@27.94,50.038
  VCC w0.2: v1(19.445,32.655) 19.3,32.8 19.3,38.6 26.7,46 26.7,48.798 J5.6@27.94,50.038
OUT23: J5.8 R14_DI3.2 U1.13 U5_DI3.5 | length 36
  Top Layer w0.2: U1.13@26.225,31.385 v1(27.515,31.385) ; J5.8@33.02,50.038 36.4,53.418 R14_DI3.2@36.4,56.6 36.4,59 34.617,60.782 U5_DI3.5@34.618,61.675
  VCC w0.2: v1(27.515,31.385) 28.4,32.27 28.4,42.6 31.752,45.952 31.752,48.77 J5.8@33.02,50.038
OUT24: J8.6 R14_DI4.2 U2.14 U5_DI4.5 | length 33.3
  Top Layer w0.2: U2.14@36.425,34.405 v1(37.695,34.405)
  Bottom Layer w0.2: U5_DI4.5@33.157,61.675 33.157,60.757 31.375,58.975 R14_DI4.2@31.375,56.6 31.375,55.275 31.7,54.95 31.7,48.72 30.48,47.5 38.2,39.78 38.2,34.91 v1(37.695,34.405)
OUT25: J8.8 R14_DI5.2 U2.4 U5_DI5.5 | length 33.8
  Top Layer w0.2: v1(29.7,33.135) U2.4@30.975,33.135
  Bottom Layer w0.2: U5_DI5.5@24.057,61.675 24.057,60.757 22.275,58.975 R14_DI5.2@22.275,56.6 22.275,55.275 24.2,53.35 24.2,48.7 28.8,44.1 28.8,34.035 v1(29.7,33.135) v1@29.565,33.135
OUT26: J8.10 R14_DI6.2 U2.6 U5_DI6.5 | length 40.9
  Top Layer w0.2: v1(29.7,30.6) 29.705,30.595 U2.6@30.975,30.595
  Bottom Layer w0.2: U5_DI6.5@14.957,61.675 14.957,60.757 13.175,58.975 R14_DI6.2@13.175,56.6 13.175,55.275 16.45,52 18.1,52 19.1,51 19.1,48.72 28,39.82 28,32.3 v1(29.7,30.6)
OUTCh7: J5.9 R17_Ch7-8.2 U1.12 U9_Ch7-8.3 | length 39.6
  Top Layer w0.2: U1.12@26.225,30.115 v1(27.515,30.115) ; J5.9@35.56,50.038 43.7,58.178 R17_Ch7-8.2@43.7,58.2 43.735,58.235 U9_Ch7-8.3@43.735,61.75
  VCC w0.2: v1(27.515,30.115) 28.8,31.4 28.8,40.5 34.3,46 34.3,48.778 J5.9@35.56,50.038
OUTCh8: J5.10 R20_Ch7-8.2 U1.11 U12_Ch7-8.3 | length 45.8
  Top Layer w0.2: U1.11@26.225,28.845 v1(27.545,28.845) ; J5.10@38.1,50.038 42.638,50.038 46.6,54 46.6,55.8 R20_Ch7-8.2@49,58.2 49,61.715 U12_Ch7-8.3@49.035,61.75
  VCC w0.2: v1(27.545,28.845) 29.2,30.5 29.2,38.99 36.83,46.62 36.83,48.768 J5.10@38.1,50.038
OUTCh9: J8.3 R17_Ch9-10.2 U2.11 U9_Ch9-10.3 | length 37.5
  Top Layer w0.2: U2.11@36.425,30.595 37.695,30.595 v1(37.7,30.6)
  Bottom Layer w0.2: v1(37.7,30.6) 39.4,32.3 39.4,46.2 38.1,47.5 45.3,54.7 45.3,57.1 R17_Ch9-10.2@46.4,58.2 46.6,58.4 46.6,61.615 U9_Ch9-10.3@46.465,61.75 ; R17_Ch9-10.2@46.3,58.2 R17_Ch9-10.2@46.465,58.365
OUTCh10: J8.4 R20_Ch9-10.2 U2.12 U12_Ch9-10.3 | length 35.5
  Top Layer w0.2: U2.12@36.425,31.865 37.665,31.865 v1(37.7,31.9)
  Bottom Layer w0.2: v1(37.7,31.9) 39,33.2 39,44.06 35.56,47.5 36.8,48.74 36.8,53.7 R20_Ch9-10.2@41.3,58.2 41.165,58.335 U12_Ch9-10.3@41.165,61.75
PE: C4.2 J6.9 J9.1 | length 88.5
  Top Layer w1: J6.9@11.63,96.95 14.68,100 43.82,100 J9.1@46.87,96.95 48.17,95.65 C4.2@53.5,95.65 53.5,100 52,100
  Bottom Layer w1: J6.9@11.63,96.95 14.7,100 43.82,100 J9.1@46.87,96.95
SPI_CLK: J1.7 R6.1 | length 5.7
  Top Layer w0.2: J1.7@6.35,26.67 7.671,27.991 11.441,27.991 R6.1@11.45,28
SPI_MISO: J2.7 R3.1 | length 12.1
  Top Layer w0.2: R3.1@40.55,28 50.74,28 J2.7@52.07,26.67
SPI_MOSI: J2.6
SPI_nCS: J2.3 R4.1 | length 5.8
  Top Layer w0.2: R4.1@46.8,38 50.8,38 51.97,36.83 J2.3@52.07,36.83
pads on no net: FID1.1 FID2.1 FID3.1 FID4.1 FID5.1 FID6.1 J1.2 J1.3 J1.4 J1.5 J1.6 J1.9 J1.10 J2.4 J2.5 J2.8 J2.9 J2.10 J3.3 J3.4 J3.5 J3.6 J3.7 J3.8 J3.9 J3.10 J4.1 J4.2 J4.3 J4.4 J4.5 J4.6 J4.7 J4.8 J4.9 J4.10 J5.2 J8.2 LBL1.0 SH-J1.0 SH-J2.0 U1.7 U2.7 U3.1 U5_DI1.6 U5_DI1.7 U5_DI1.12 U5_DI1.13 U5_DI2.6 U5_DI2.7 U5_DI2.12 U5_DI2.13 U5_DI3.6 U5_DI3.7 U5_DI3.12 U5_DI3.13 U5_DI4.6 U5_DI4.7 U5_DI4.12 U5_DI4.13 U5_DI5.6 U5_DI5.7 U5_DI5.12 U5_DI5.13 U5_DI6.6 U5_DI6.7 U5_DI6.12 U5_DI6.13 U9_Ch7-8.5 U9_Ch9-10.5 U12_Ch7-8.5 U12_Ch9-10.5

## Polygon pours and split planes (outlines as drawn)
DGND on Top Layer "TOP_LAYER_DGND_P018" (solid, remove dead copper, pour order 18): 1,61.3 2,62.3 56,62.3 57,61.3 57,6 56,5 2,5 1,6
FGND on Top Layer "FGND_TOP" (solid, remove dead copper, pour order 16): 57,66.4 57.8,67.2 57.8,92.2 57,93 51,93 50,92 50,86.83 49.17,86 46.8,86 45.7,84.9 45.7,83.6 46.8,82.5 53.5,82.5 55,81 55,72 10.8,72 10.8,75.2 10.4,75.6 7,75.6 7,82 7.5,82.5 11.7,82.5 12.7,83.5 12.7,85 11.7,86 6,86 2,82 2,67.4 3,66.4
DGND on GND "GND_DGND_P022" (solid, remove dead copper, pour order 22): 1,61.3 2,62.3 56,62.3 57,61.3 57,6 56,5 2,5 1,6
FGND on GND "FGND_MID-1" (solid, remove dead copper, pour order 20): 57,66.4 57.8,67.2 57.8,92.2 57,93 51,93 50,92 50,86.83 49.17,86 46.8,86 45.7,84.9 45.7,83.6 46.8,82.5 53.5,82.5 55,81 55,73 54,72 10.8,72 10.8,75.2 10.4,75.6 7,75.6 7,82 7.5,82.5 11.7,82.5 12.7,83.5 12.7,85 11.7,86 6,86 2,82 2,67.4 3,66.4
DGND on Bottom Layer "BOTTOM_LAYER_DGND_P026" (solid, remove dead copper, pour order 26): 1,61.3 2,62.3 56,62.3 57,61.3 57,6 56,5 2,5 1,6
FGND on Bottom Layer "FGND_BOTTOM" (solid, remove dead copper, pour order 24): 57,66.4 57.8,67.2 57.8,92.2 57,93 51,93 50,92 50,86.83 49.17,86 46.8,86 45.7,84.9 45.7,83.6 46.8,82.5 53.5,82.5 55,81 55,73 54,72 10.8,72 10.8,75.2 10.4,75.6 7,75.6 7,82 7.5,82.5 11.7,82.5 12.7,83.5 12.7,85 11.7,86 6,86 2,82 2,67.4 3,66.4
3V3 on VCC "VCC_3V3_P030" (solid, remove dead copper, pour order 30): 1,61.3 2,62.3 56,62.3 57,61.3 57,6 56,5 2,5 1,6
FGND on VCC "FGND_MID-2" (solid, remove dead copper, pour order 28): 57,66.4 57.8,67.2 57.8,92.2 57,93 51,93 50,92 50,86.83 49.17,86 46.8,86 45.7,84.9 45.7,83.6 46.8,82.5 53.5,82.5 55,81 55,73 54,72 10.8,72 10.8,75.2 10.4,75.6 7,75.6 7,82 7.5,82.5 11.7,82.5 12.7,83.5 12.7,85 11.7,86 6,86 2,82 2,67.4 3,66.4

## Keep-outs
Keep-Out Layer:
  the board outline again, w0.5
  text ".Layer_Name" at 14.656,-21.806 h1.52

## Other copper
Top Layer:
  rectangle net PE: 50.1,98 54,101.9
  text ".Layer_Name" at 14.656,-21.806 h1.52
GND:
  text ".Layer_Name" at 14.656,-21.806 h1.52
VCC:
  text ".Layer_Name" at 14.656,-21.806 h1.52
Bottom Layer:
  text ".Layer_Name" at 14.656,-21.806 h1.52

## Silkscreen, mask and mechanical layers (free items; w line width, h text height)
Top Overlay:
  lines w0.15: 14.65,47.775 15.85,47.775 ; 14.85,47.55 15.65,47.55 ; 15.05,47.325 15.45,47.325 ; 15.25,47.775 15.25,48.25 ; 42.65,45 43.85,45 ; 42.85,44.775 43.65,44.775 ; 43.05,44.55 43.45,44.55 ; 43.25,45 43.25,45.475
  text "PE" at 50.4,96.5 h2
  text "Ch  1   2   3   4   5   6   7   8" at 16.75,51.5 h2
  text "Ch  9  10  11 12 13 14 15 16" at 16.5,44.5 h2
  text "J4" at 47.244,43.815 h1
  text "J2" at 53.086,43.815 h1
  text "J1" at 4.25,43.75 h1
  text "J3" at 9.75,43.75 h1
  text "1" at 6.096,43.18 h0.89
  text "21" at 8.255,43.18 h0.89
  text "40" at 49.022,43.18 h0.76
  text "20" at 51.435,43.18 h0.76
  text "3V3" at 0.75,41 h2
  text "5V" at 10,41 h2
  text "GND" at 53.25,41 h2
  text "GND" at 10,38.5 h2
  text "BrWi / 1-8" at 53.5,38 h1.8
  text "nCS" at 53.25,36 h2
  text "MOSI" at 53.25,28.5 h2
  text "CLK" at 1.75,26 h2
  text "MISO" at 53.25,26 h2
  text "BrWi / 9-16" at 1.5,23 h1.8
  text "31" at 49,17.25 h0.76
  text "11" at 51.5,17.25 h0.76
  text "10" at 5.842,17.018 h0.76
  text "30" at 8.382,17.018 h0.76
  text "TIDA-01508/09" at 39.75,10.95 h2
  text ".Layer_Name" at 14.656,-21.806 h1.52
Bottom Overlay:
  text ".Layer_Name" at 14.656,-21.806 h1.52
Top Paste:
  text ".Layer_Name" at 14.656,-21.806 h1.52
Bottom Paste:
  text ".Layer_Name" at 14.656,-21.806 h1.52
Top Solder:
  text ".Layer_Name" at 14.656,-21.806 h1.52
  text ".Layer_Name" at 14.656,-21.806 h1.52
Bottom Solder:
  text ".Layer_Name" at 14.656,-21.806 h1.52
Drill Guide:
  text ".Layer_Name" at 14.656,-21.806 h1.52
M1 Board Outline:
  the board outline again, w0.254
  text ".Layer_Name" at 14.656,-21.806 h1.52
M2 Board Dimensions:
  lines w0.25: -4,1.5 -3.5,0 ; -4,101.5 -3.5,103 ; -3.75,0 -3.25,0 ; -3.75,103 -3.25,103 ; -3.5,47.722 -3.5,0 ; -3.5,55.278 -3.5,103 ; -3,1.5 -3.5,0 ; -3,101.5 -3.5,103 ; 0,-3.75 0,-3.25 ; 1.5,-4 0,-3.5 ; 1.5,-3 0,-3.5 ; 24.722,-3.5 0,-3.5 ; 33.778,-3.5 58.5,-3.5 ; 57,-4 58.5,-3.5 ; 57,-3 58.5,-3.5 ; 58.5,-3.75 58.5,-3.25
  text "103mm" at -2.6,47.976 h1.5 r90
  text "58.5mm" at 24.976,-4.4 h1.5
  text ".Layer_Name" at 14.656,-21.806 h1.52
M3 3D STEP Top:
  text ".Layer_Name" at 14.656,-21.806 h1.52
M4 3D STEP Bottom:
  text ".Layer_Name" at 14.656,-21.806 h1.52
M5 Assembly Top:
  lines w0.254: -7.417,-23.626 160.223,-23.626 ; -7.417,-18.462 160.274,-18.462 ; -7.417,-13.297 -7.417,-28.791 94.31,-28.791 160.274,-28.791 160.274,-13.297 -7.404,-13.297 -7.404,-28.791 32.614,-28.791 ; 55.194,-28.791 55.194,-13.297 ; 87.376,-18.462 87.376,-13.297 ; 108.712,-18.462 108.712,-13.297 ; 124.511,-28.956 124.511,-23.804
  text "COMPONENTS MARKED 'DNP' SHOULD NOT BE POPULATED." at 29.299,-8.09 h1.52
  text "ASSEMBLY VARIANT:" at 29.286,-11.024 h1.52
  text ".VariantName" at 55.601,-11.024 h1.52
  text "PCB VIEWED FROM TOP SIDE" at -5.804,-16.654 h1.52
  text "BOARD #:" at 57.099,-16.654 h1.52
  text ".PRJ_Number" at 70.955,-16.654 h1.52
  text "REV:" at 92.405,-16.654 h1.52
  text ".PCB_Rev" at 99.809,-16.654 h1.52
  text "SVN REV:" at 113.69,-16.654 h1.52
  text ".VersionControl_RevNumber" at 126.543,-16.654 h1.52
  text "TID #:" at 57.099,-21.819 h1.52
  text ".TID" at 70.955,-21.819 h1.52
  text "PLOT NAME =" at -5.804,-27.034 h1.52
  text ".plot_File_Name" at 14.656,-27.034 h1.52
  text "GENERATED    :" at 57.15,-27.034 h1.52
  text ".Print_Date" at 79.235,-27.034 h1.52
  text ".Print_Time" at 97.752,-27.034 h1.52
  text "TEXAS INSTRUMENTS" at 129.87,-27.034 h1.52
M6 Assembly Bottom:
  lines w0.254: -7.429,-18.474 160.261,-18.474 ; -7.379,-23.639 160.261,-23.639 ; 28.334,-28.969 28.334,-23.817 ; 44.133,-18.474 44.133,-13.31 ; 65.468,-18.474 65.468,-13.31 ; 97.65,-28.804 97.65,-13.31 ; 120.231,-28.804 160.249,-28.804 160.249,-13.31 -7.429,-13.31 -7.429,-28.804 58.534,-28.804 160.261,-28.804 160.261,-13.31
  text "COMPONENTS MARKED 'DNP' SHOULD NOT BE POPULATED." at 154.991,-8.077 h1.52
  text ".VariantName" at 128.473,-11.024 h1.52
  text "ASSEMBLY VARIANT:" at 154.864,-11.024 h1.52
  text ".VersionControl_RevNumber" at 26.302,-16.667 h1.52
  text "SVN REV:" at 39.154,-16.667 h1.52
  text ".PCB_Rev" at 53.035,-16.667 h1.52
  text "REV:" at 60.439,-16.667 h1.52
  text ".PRJ_Number" at 81.89,-16.667 h1.52
  text "BOARD #:" at 95.745,-16.667 h1.52
  text "PCB VIEWED FROM BOTTOM SIDE" at 158.648,-16.667 h1.52
  text ".TID" at 81.89,-21.831 h1.52
  text "TID #:" at 95.745,-21.831 h1.52
  text "TEXAS INSTRUMENTS" at 22.974,-27.047 h1.52
  text ".Print_Time" at 55.093,-27.047 h1.52
  text ".Print_Date" at 73.609,-27.047 h1.52
  text "GENERATED    :" at 95.694,-27.047 h1.52
  text ".plot_File_Name" at 138.189,-27.047 h1.52
  text "PLOT NAME =" at 158.648,-27.047 h1.52
M9 Title Sheet:
  drawing of 57 lines, arcs and shapes, not listed
  text "1" at 18.792,204.127 h1.78
  text "2" at 82.182,204.127 h1.78
  text "3" at 145.411,204.127 h1.78
  text "4" at 209.08,204.127 h1.78
  text "5" at 272.555,204.127 h1.78
  text "6" at 336.182,204.127 h1.78
  text "A" at -10.579,175.095 h1.78
  text "A" at 365.341,175.095 h1.78
  text "B" at -10.579,114.643 h1.78
  text "B" at 365.341,114.643 h1.78
  text "C" at -10.579,54.318 h1.78
  text "C" at 365.341,54.318 h1.78
  text "PROJECT TITLE:" at 288.125,7.048 h1.14
  text ".PRJ_Title" at 289.395,3.662 h1.78
  text "DESIGNED FOR:" at 288.125,-0.597 h1.14
  text ".PRJ_Customer" at 289.395,-4.153 h1.78
  text "D" at -10.579,-5.88 h1.78
  text "D" at 365.341,-5.88 h1.78
  text "FILE NAME:" at 288.125,-8.217 h1.14
  text ".PCB_File_Name_No_Path" at 289.395,-11.265 h1.78
  text "Texas Instruments (TI) and/or its licensors do not warrant the accuracy or completeness of this specification" at 161.9,-15.376 h1.14
  text "ENGINEER:" at 288.125,-15.583 h1.14
  text "LAYOUT BY:" at 326.352,-15.583 h1.14
  text "or any information contained therein. TI and/or its licensors do not warrant that this design will meet" at 160.757,-18.237 h1.14
  text ".PRJ_Engineer" at 289.395,-19.52 h1.78
  text ".PCB_Layout" at 327.635,-19.52 h1.78
  text "the specifications, will be suitable for your application or fit for any particular purpose, or will operate in" at 160.757,-21.099 h1.14
  text ".Layer_Name" at 14.656,-21.806 h1.52
  text "ALTIUM DESIGNER VERSION:" at 326.352,-23.457 h1.14
  text "an implementation. TI and/or its licensors do not warrant that the design is production worthy. You should" at 160.757,-23.961 h1.14
  text "completely validate and test your design implementation to confirm the system functionality for your application." at 161.9,-26.822 h1.14
  text ".print_Scale" at 289.395,-26.843 h1.78
  text ".Application_BuildNumber" at 327.635,-26.843 h1.78
  text "1" at 18.792,-32.093 h1.78
  text "2" at 82.182,-32.093 h1.78
  text "3" at 145.411,-32.093 h1.78
  text "4" at 209.08,-32.093 h1.78
  text "5" at 272.555,-32.093 h1.78
  text "6" at 336.182,-32.093 h1.78
M10 Fab Notes:
  drawing of 189 lines, arcs and shapes, not listed
  text "DESIGN INFORMATION" at 314.503,161.447 h1.52
  text "MIN. TRACK WIDTH:" at 298.131,158.091 h1.52
  text "8" at 325.976,158.091 h1.52
  text "MIL" at 329.907,158.091 h1.52
  text "MIN. CLEARANCE:" at 298.131,154.938 h1.52
  text "0.15" at 324.002,154.94 h1.52
  text "mm" at 329.907,154.938 h1.52
  text "MIN. VIA PAD SIZE:" at 298.131,151.785 h1.52
  text "20" at 325.214,151.785 h1.52
  text "MIL" at 329.907,151.785 h1.52
  text "0.05mm (2MIL)" at 315.784,148.486 h1.52
  text "MINIMUM ANNULAR RING" at 289.769,148.277 h1.52
  text "EXTERNAL" at 333.768,148.277 h1.52
  text "PER" at 294.849,145.48 h1.52
  text "IPC-D-275 CLASS 2 LEVEL C" at 300.437,145.48 h1.52
  text "MIL, HOLES" at 338.238,142.928 h1.52
  text "+/-" at 328.27,142.709 h1.52
  text "+/-" at 349.961,142.709 h1.52
  text "REGISTRATION TOLERANCES:" at 289.769,142.682 h1.52
  text "METAL" at 320.243,142.682 h1.52
  text "5" at 334.879,142.683 h1.52
  text "3" at 356.037,142.683 h1.52
  text "MIL" at 358.99,142.682 h1.52
  text "HOLE SIZE TOLERANCE (UNLESS OTHERWISE SPECIFIED):" at 289.769,140.185 h1.52
  text "+/-" at 349.961,140.112 h1.52
  text "3" at 356.037,140.085 h1.52
  text "MIL" at 358.99,140.085 h1.52
  text "MATERIAL:" at 287.87,136.589 h1.52
  text "FR-4 High Tg" at 312.926,133.324 h1.52
  text "X" at 309.257,133.122 h1.52
  text "FR-408" at 298.563,133.007 h1.52
  text "OTHER" at 336.358,133.007 h1.52
  text "62 MIL (1.6mm) +/-10%" at 306.694,129.374 h1.52
  text "X" at 303.643,129.312 h1.52
  text "THICKNESS:" at 289.769,129.165 h1.52
  text "OTHER" at 339.33,129.165 h1.52
  text "TOLERANCE:" at 289.769,125.652 h1.52
  text "X" at 311.314,125.652 h1.52
  text "ANSI IPC-6012 TYPE 3 CLASS 2" at 315.836,125.652 h1.52
  text "OTHER +/-" at 315.835,121.989 h1.52
  text "BOW & TWIST:" at 289.769,118.302 h1.52
  text "X" at 311.314,118.302 h1.52
  text "ANSI IPC-6012 TYPE 3 CLASS 2" at 315.836,118.302 h1.52
  text "OTHER +/-" at 315.835,114.576 h1.52
  text "DRILLING:" at 287.87,111.258 h1.52
  text "NC_DRILL FILES" at 332.599,108.586 h1.52
  text "REFERENCE:" at 289.769,108.486 h1.52
  text "X" at 306.463,108.484 h1.52
  text "AS SHOWN" at 310.984,108.486 h1.52
  text "X" at 329.348,108.486 h1.52
  text "OTHER" at 340.168,104.873 h1.52
  text "PTH COPPER THICKNESS:" at 289.761,104.783 h1.52
  text "X" at 318.697,104.783 h1.52
  text "20-30 um" at 321.948,104.783 h1.52
  text "BOARD FINISH:" at 287.87,101.034 h1.52
  text "SILKSCREEN:" at 291.812,98.237 h1.52
  text "X" at 316.14,98.237 h1.52
  text "TOP" at 319.112,98.237 h1.52
  text "BOTTOM" at 332.091,98.237 h1.52
  text "SILKSCREEN COLOR:" at 291.812,94.295 h1.52
  text "X" at 316.115,94.295 h1.52
  text "WHITE" at 319.112,94.295 h1.52
  text "OTHER" at 332.091,94.295 h1.52
  text "X" at 319.442,90.652 h1.52
  text "GREEN" at 322.439,90.652 h1.52
  text "OTHER" at 338.136,90.652 h1.52
  text "SOLDER RESIST COLOR:" at 291.812,90.477 h1.52
  text "X" at 319.442,86.734 h1.52
  text "MATTE" at 322.439,86.734 h1.52
  text "SEMI-GLOSS" at 338.125,86.717 h1.52
  text "IMMERSION GOLD (ENIG)" at 314.819,82.345 h1.52
  text "ENEPIG" at 348.793,82.162 h1.52
  text "SURFACE FINISH:" at 287.87,82.136 h1.52
  text "X" at 310.298,82.136 h1.52
  text "IMM. TIN/SILVER OR EQUIV" at 296.24,78.649 h1.52
  text "OTHER" at 332.599,78.549 h1.52
  text "ARRAY/PANEL:" at 287.87,74.602 h1.52
  text "CUT AND TRIM PER M1 BOARD OUTLINE" at 314.819,74.393 h1.52
  text "N.C. ROUTE" at 314.819,70.94 h1.52
  text "X" at 332.295,70.94 h1.52
  text "V. SCORE" at 336.816,70.94 h1.52
  text "CERTIFICATION:" at 287.87,67.66 h1.52
  text "MATERIALS AND WORKMANSHIP FOR ALL PCBS" at 306.285,67.66 h1.52
  text "TO MEET OR EXCEED THE REQUIREMENTS OF:" at 306.285,65.271 h1.52
  text "X" at 297.078,62.003 h1.52
  text "ANSI IPC-A-600F CLASS ->" at 300.329,62.003 h1.52
  text "X" at 342.188,62.003 h1.52
  text "2" at 344.982,62.003 h1.52
  text "1" at 336.981,61.965 h1.52
  text "3" at 353.973,61.965 h1.52
  text "X" at 317.702,58.252 h1.52
  text "RoHS" at 320.953,58.252 h1.52
  text "OTHER" at 337.321,58.252 h1.52
  text "PER ORDER" at 347.407,58.252 h1.52
  text "ALL BOARDS MUST MEET OR EXCEED UL94-V0 REQUIREMENTS." at 288.569,54.345 h1.52
  text "PCB MUST BEAR THE UL94V-0 UL REGISTERED MATERIAL ID NUMBER" at 288.569,51.397 h1.52
  text "ADDITIONAL REQUIREMENTS:" at 287.87,47.094 h1.52
  text "MICROSECTION:" at 289.769,44.373 h1.52
  text "YES" at 312.775,44.373 h1.52
  text "REQUIRED" at 334.657,40.707 h1.52
  text "BARE BOARD ELEC. TEST:" at 289.769,40.634 h1.52
  text "NONE" at 322.935,40.634 h1.52
  text "X" at 331.66,40.634 h1.52
  text "PER ORDER" at 349.693,40.634 h1.52
  text "XX MIL VIAS REQUIRE NON-CONDUCTIVE FILL AND PLANARIZE" at 294.04,35.428 h1.5
  text "XX MIL VIAS REQUIRE CONDUCTIVE FILL AND PLANARIZE" at 294.243,32.787 h1.52
  text "OUTER XX MIL VIAS REQUIRE 50 OHM SINGLE-ENDED IMPEDANCE" at 294.218,28.637 h1.47
  text "LAYER 2 & 3 (INNER LAYERS) XX MIL WIDE, XX MIL SPACE / TRACES REQUIRE 100 OHM DIFFERENTIAL IMPEDANCE" at 294.015,22.65 h1.52
  text ".Layer_Name" at 14.656,-21.806 h1.52
M11 Gerber Information:
  lines w0.254: -7.417,-23.626 160.223,-23.626 ; -7.417,-18.462 160.274,-18.462 ; -7.417,-13.297 -7.417,-28.791 94.31,-28.791 160.274,-28.791 160.274,-13.297 -7.404,-13.297 -7.404,-28.791 32.614,-28.791 ; 55.194,-28.791 55.194,-13.297 ; 87.376,-18.462 87.376,-13.297 ; 108.712,-18.462 108.712,-13.297 ; 124.511,-28.956 124.511,-23.804
  text "ALL ARTWORK VIEWED FROM TOP SIDE" at -5.804,-16.654 h1.52
  text "BOARD #:" at 57.099,-16.654 h1.52
  text ".PRJ_Number" at 70.955,-16.654 h1.52
  text "REV:" at 92.405,-16.654 h1.52
  text ".PCB_Rev" at 99.809,-16.654 h1.52
  text "SVN REV:" at 113.69,-16.654 h1.52
  text ".VersionControl_RevNumber" at 126.543,-16.654 h1.52
  text "LAYER NAME =" at -5.804,-21.806 h1.52
  text "TID #:" at 57.099,-21.819 h1.52
  text ".TID" at 70.955,-21.819 h1.52
  text "PLOT NAME =" at -5.804,-27.034 h1.52
  text ".plot_File_Name" at 14.656,-27.034 h1.52
  text "GENERATED    :" at 57.15,-27.034 h1.52
  text ".Print_Date" at 79.235,-27.034 h1.52
  text ".Print_Time" at 97.752,-27.034 h1.52
  text "TEXAS INSTRUMENTS" at 129.87,-27.034 h1.52
M12 Stackup:
  drawing of 295 lines, arcs and shapes, not listed
  text "Layer" at 248.865,198.882 h1.52
  text "Name" at 259.277,198.882 h1.52
  text "Material" at 282.892,198.882 h1.52
  text "Thickness" at 304.731,198.882 h1.52
  text "Constant" at 321.236,198.882 h1.52
  text "Board Layer Stack" at 335.711,198.882 h1.52
  text "1" at 248.865,195.834 h1.52
  text "Top Overlay" at 259.277,195.834 h1.52
  text "2" at 248.865,192.786 h1.52
  text "Top Solder" at 259.277,192.786 h1.52
  text "Solder Resist" at 282.892,192.786 h1.52
  text "0,010mm" at 304.731,192.786 h1.52
  text "3,5" at 321.236,192.786 h1.52
  text "3" at 248.865,189.738 h1.52
  text "Top Layer" at 259.277,189.738 h1.52
  text "Copper" at 282.892,189.738 h1.52
  text "0,036mm" at 304.731,189.738 h1.52
  text "4" at 248.865,186.69 h1.52
  text "Dielectric 1" at 259.277,186.69 h1.52
  text "FR-4" at 282.892,186.69 h1.52
  text "0,203mm" at 304.731,186.69 h1.52
  text "4,2" at 321.236,186.69 h1.52
  text "5" at 248.865,183.642 h1.52
  text "GND" at 259.277,183.642 h1.52
  text "Copper" at 282.892,183.642 h1.52
  text "0,036mm" at 304.731,183.642 h1.52
  text "6" at 248.865,180.594 h1.52
  text "Dielectric 2" at 259.277,180.594 h1.52
  text "FR-4" at 282.892,180.594 h1.52
  text "1,016mm" at 304.731,180.594 h1.52
  text "4,2" at 321.236,180.594 h1.52
  text "7" at 248.865,177.546 h1.52
  text "VCC" at 259.277,177.546 h1.52
  text "Copper" at 282.892,177.546 h1.52
  text "0,036mm" at 304.731,177.546 h1.52
  text "8" at 248.865,174.498 h1.52
  text "Dielectric 3" at 259.277,174.498 h1.52
  text "FR-4" at 282.892,174.498 h1.52
  text "0,203mm" at 304.731,174.498 h1.52
  text "4,2" at 321.236,174.498 h1.52
  text "9" at 248.865,171.45 h1.52
  text "Bottom Layer" at 259.277,171.45 h1.52
  text "Copper" at 282.892,171.45 h1.52
  text "0,036mm" at 304.731,171.45 h1.52
  text "10" at 248.865,168.402 h1.52
  text "Bottom Solder" at 259.277,168.402 h1.52
  text "Solder Resist" at 282.892,168.402 h1.52
  text "0,010mm" at 304.731,168.402 h1.52
  text "3,5" at 321.236,168.402 h1.52
  text "11" at 248.865,165.354 h1.52
  text "Bottom Overlay" at 259.277,165.354 h1.52
  text ".Layer_Name" at 14.656,-21.806 h1.52
M13 Component Bodies Top:
  text ".Layer_Name" at 14.656,-21.806 h1.52
M14 Component Bodies Bottom:
  text ".Layer_Name" at 14.656,-21.806 h1.52
M15 Courtyards Top:
  text ".Layer_Name" at 14.656,-21.806 h1.52
M16 Courtyards Bottom:
  text ".Layer_Name" at 14.656,-21.806 h1.52
Drill Drawing:
  circle w0.254: c204.343,157.612 r0.702
  lines w0.254: 203.642,137.964 204.343,138.315 205.045,137.964 204.694,138.665 205.045,139.367 204.343,139.016 203.642,139.367 203.993,138.665 203.642,137.964 ; 203.642,142.525 205.045,142.525 204.343,141.121 203.642,142.525 ; 203.642,144.279 205.045,144.279 205.045,145.683 203.642,145.683 203.642,144.279 ; 203.642,147.788 203.993,147.788 204.343,147.437 204.694,147.788 205.045,147.788 204.694,148.139 205.045,148.49 204.694,148.49 204.343,148.84 203.993,148.49 203.642,148.49 203.993,148.139 203.642,147.788 ; 203.642,150.595 203.642,150.946 203.993,151.296 203.642,151.647 203.642,151.998 203.993,151.998 204.343,151.647 204.694,151.998 205.045,151.998 205.045,151.647 204.694,151.296 205.045,150.946 205.045,150.595 204.694,150.595 204.343,150.946 203.993,150.595 203.642,150.595 ; 203.642,154.103 203.993,154.103 203.993,153.752 204.694,153.752 204.694,154.103 205.045,154.103 205.045,154.805 204.694,154.805 204.694,155.156 203.993,155.156 203.993,154.805 203.642,154.805 203.642,154.103
  lines w0.305: 202.369,137.016 284.449,137.016 ; 202.369,159.121 284.449,159.121 ; 210.951,133.859 210.951,162.278 ; 219.384,133.859 219.384,162.278 ; 235.553,133.859 235.553,162.278 ; 242.135,133.859 242.135,162.278 ; 251.664,133.859 251.664,162.278 ; 270.062,133.859 270.062,162.278 ; 202.369,133.859 284.449,133.859 284.449,162.278 202.369,162.278 202.369,133.859
  text "Symbol" at 204.264,160.068 h1.83
  text "Quantity" at 211.898,160.068 h1.83
  text "Finished Hole Size" at 220.331,160.068 h1.83
  text "Plated" at 236.5,160.068 h1.83
  text "Hole Type" at 243.082,160.068 h1.83
  text "Drill Layer Pair" at 252.611,160.068 h1.83
  text "Hole Tolerance" at 271.009,160.068 h1.83
  text "4" at 211.898,156.91 h1.52
  text "2,500mm (98,43mil)" at 220.331,156.91 h1.52
  text "NPTH" at 236.5,156.91 h1.52
  text "Round" at 243.082,156.91 h1.52
  text "Top Layer - Bottom Layer" at 252.611,156.91 h1.52
  text "129" at 211.898,153.752 h1.52
  text "0,200mm (7,87mil)" at 220.331,153.752 h1.52
  text "PTH" at 236.5,153.752 h1.52
  text "Round" at 243.082,153.752 h1.52
  text "Top Layer - Bottom Layer" at 252.611,153.752 h1.52
  text "1" at 211.898,150.595 h1.52
  text "0,400mm (15,75mil)" at 220.331,150.595 h1.52
  text "PTH" at 236.5,150.595 h1.52
  text "Round" at 243.082,150.595 h1.52
  text "Top Layer - Bottom Layer" at 252.611,150.595 h1.52
  text "4" at 211.898,147.437 h1.52
  text "1,020mm (40,16mil)" at 220.331,147.437 h1.52
  text "PTH" at 236.5,147.437 h1.52
  text "Round" at 243.082,147.437 h1.52
  text "Top Layer - Bottom Layer" at 252.611,147.437 h1.52
  text "20" at 211.898,144.279 h1.52
  text "1,100mm (43,31mil)" at 220.331,144.279 h1.52
  text "PTH" at 236.5,144.279 h1.52
  text "Round" at 243.082,144.279 h1.52
  text "Top Layer - Bottom Layer" at 252.611,144.279 h1.52
  text "40" at 211.898,141.121 h1.52
  text "1,150mm (45,28mil)" at 220.331,141.121 h1.52
  text "PTH" at 236.5,141.121 h1.52
  text "Round" at 243.082,141.121 h1.52
  text "Top Layer - Bottom Layer" at 252.611,141.121 h1.52
  text "20" at 211.898,137.964 h1.52
  text "1,400mm (55,12mil)" at 220.331,137.964 h1.52
  text "PTH" at 236.5,137.964 h1.52
  text "Round" at 243.082,137.964 h1.52
  text "Top Layer - Bottom Layer" at 252.611,137.964 h1.52
  text "+/-0,200mm" at 271.009,137.964 h1.52
  text "218 Total" at 211.898,134.806 h1.52
  text ".Layer_Name" at 14.656,-21.806 h1.52
Mechanical 17:
  text ".Layer_Name" at 14.656,-21.806 h1.52
Mechanical 18:
  text ".Layer_Name" at 14.656,-21.806 h1.52
Mechanical 19:
  text ".Layer_Name" at 14.656,-21.806 h1.52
